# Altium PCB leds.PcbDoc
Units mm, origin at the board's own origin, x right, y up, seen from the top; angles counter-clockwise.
Board outline 80 x 58 mm, 2 copper layers (Top Layer, Bottom Layer), stack 1.579 mm thick; 53 components, 21 nets, 131 pads, 173 vias.
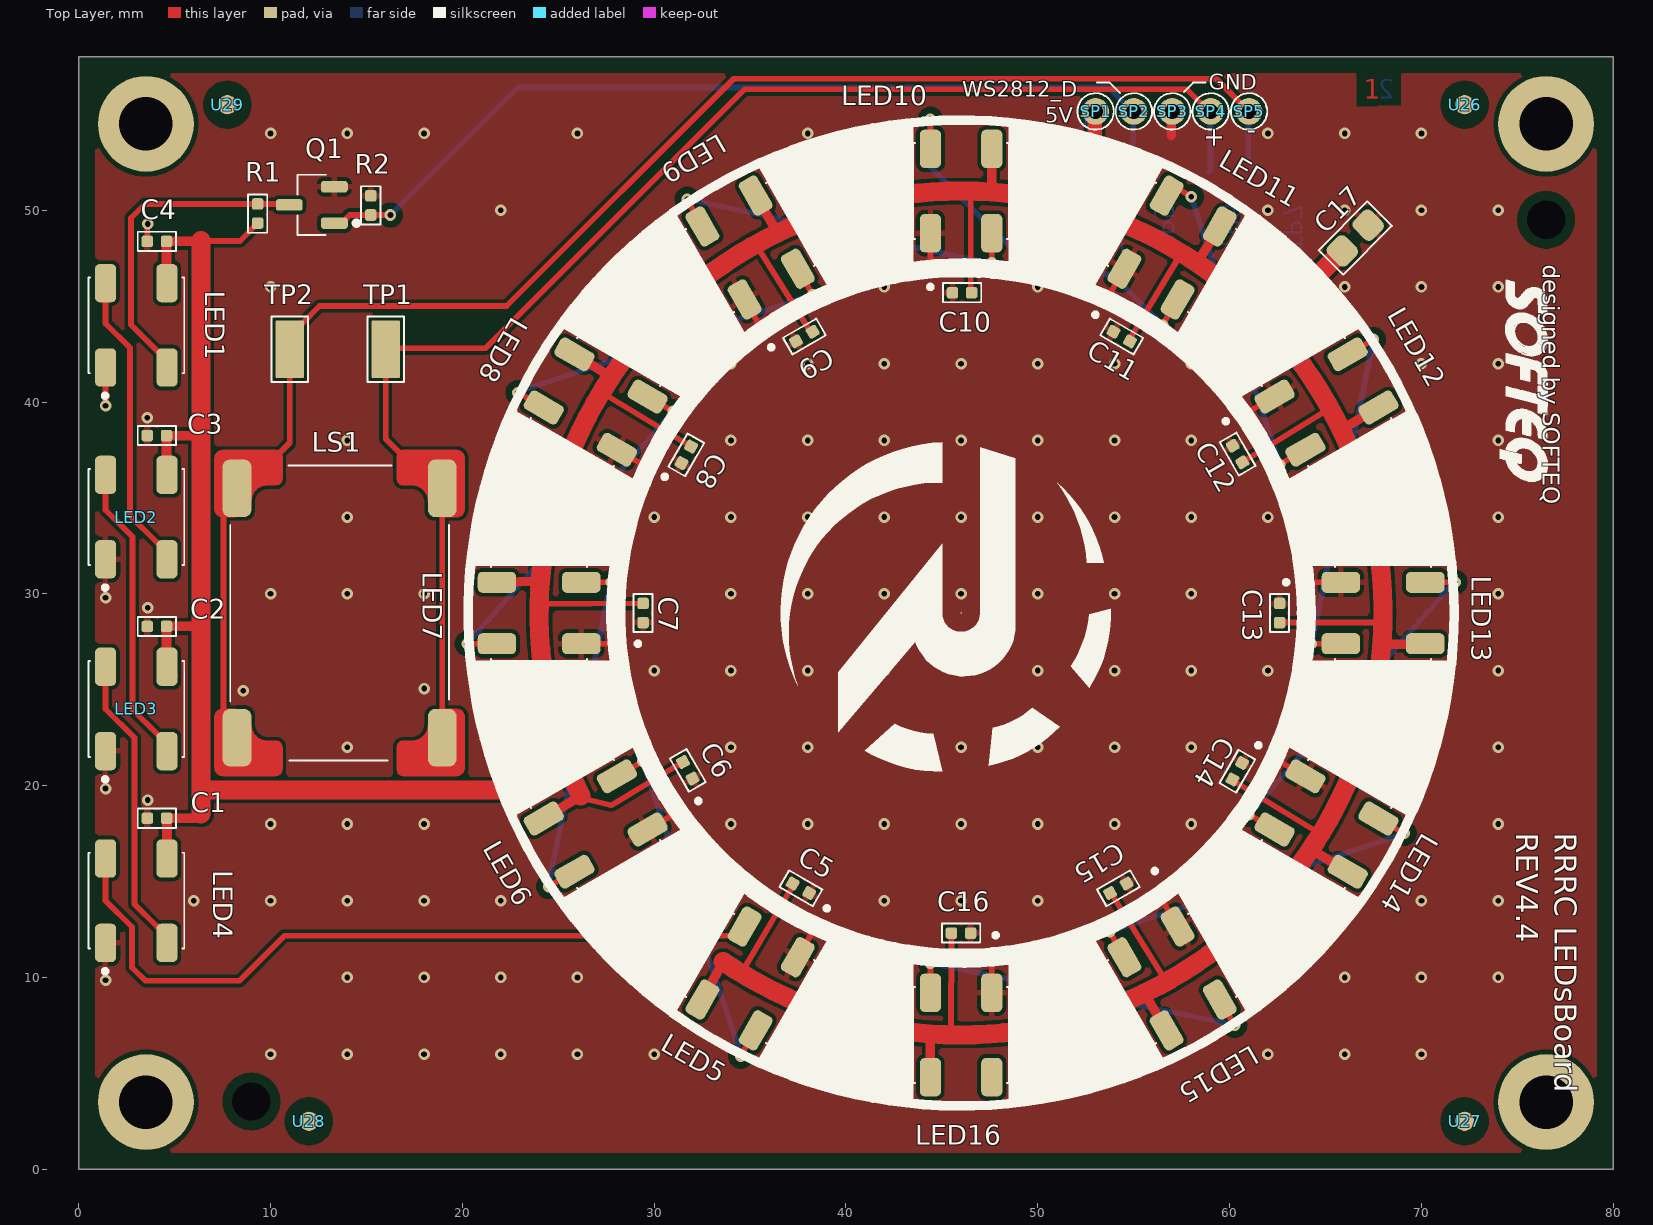
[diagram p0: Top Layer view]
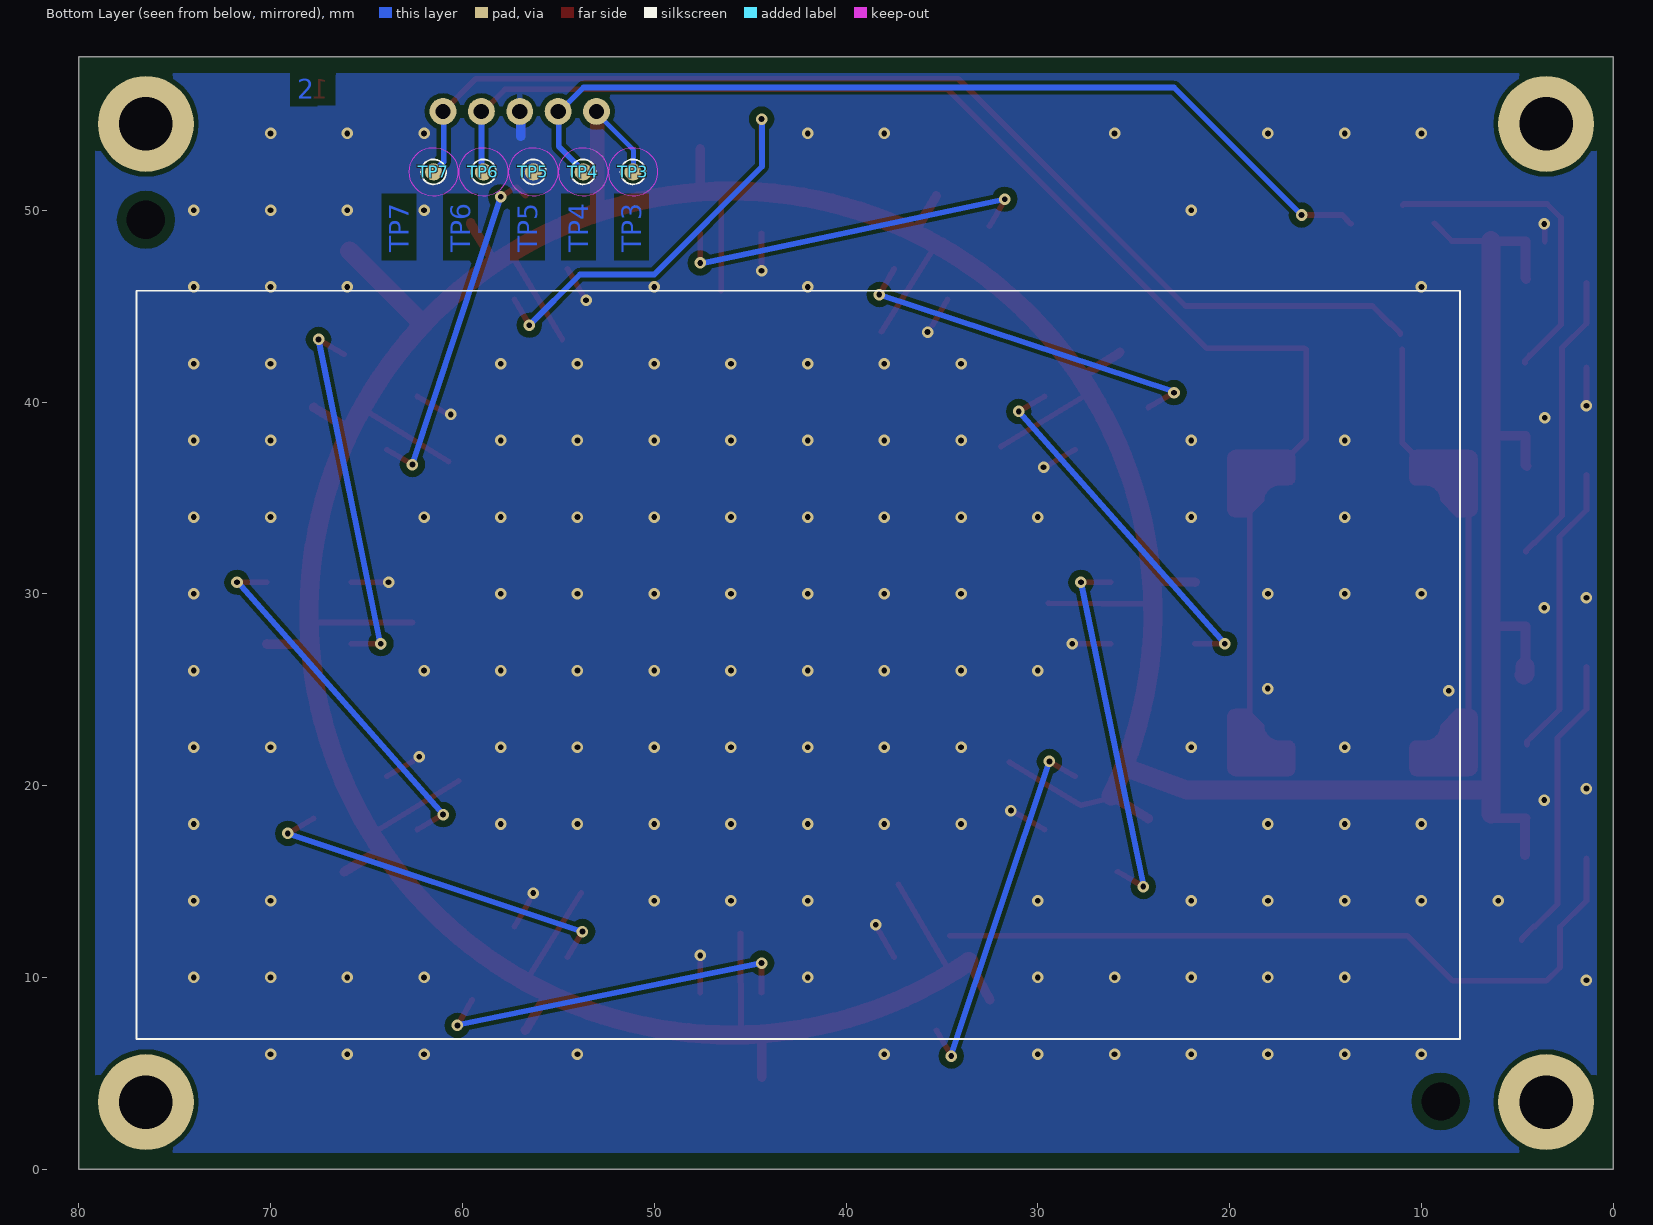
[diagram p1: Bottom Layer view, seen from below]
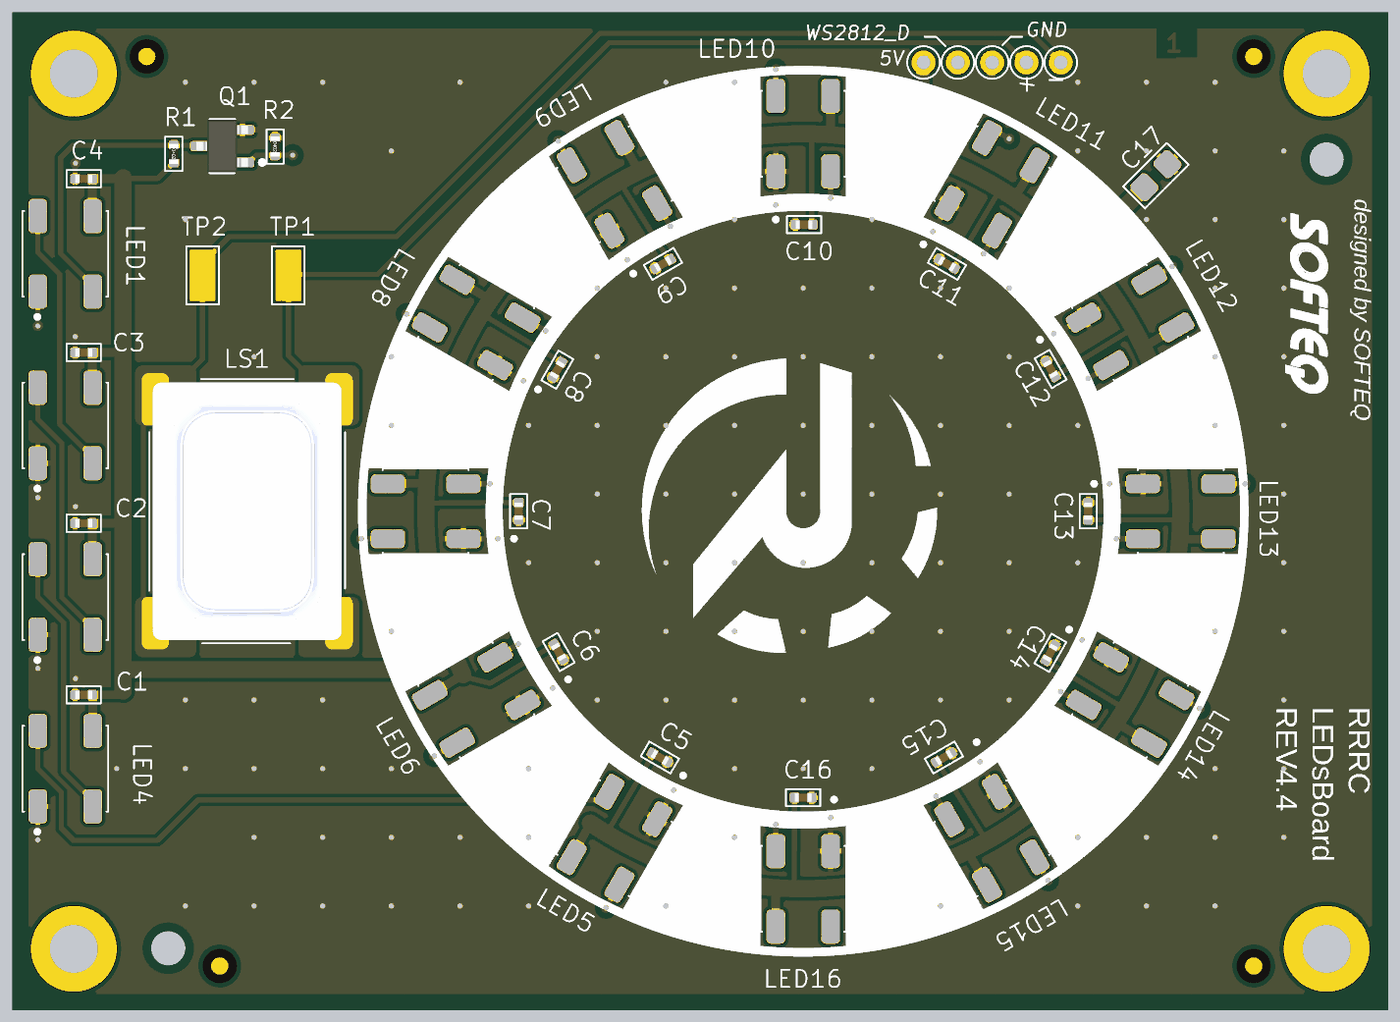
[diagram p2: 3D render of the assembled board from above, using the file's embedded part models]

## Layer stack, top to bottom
Top Solder: solder mask 0.02, Solder Resist, Dk 3.5
Top Layer: signal copper 0.04
Dielectric 1: core 1.4986, Core-043, Dk 4.3
Bottom Layer: signal copper 0.04
Bottom Solder: solder mask 0.02, Solder Resist, Dk 3.5

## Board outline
0,0 0,58 80,58 80,0

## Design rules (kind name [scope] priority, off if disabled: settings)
BoardOutlineClearance [OnSignal] p1: gap=0.85 ignorepadtopadclearanceinfootprint=FALSE
Clearance Clearance_samenet [IsPad vs IsVia] p1: gap=0.2 ignorepadtopadclearanceinfootprint=FALSE except(0.5: Fill-Fill Fill-Poly Fill-Region Poly-Poly Poly-Region Region-Region)
Clearance [All] p2: gap=0.2 ignorepadtopadclearanceinfootprint=FALSE except(0.25: THPad-Poly; 0.5: Poly-Hole)
ComponentClearance [All] p1 off: gap=0.254 collisioncheckmode=3 verticalgap=0.254 showdistances=FALSE
MinimumSolderMaskSliver [All] p1: minsoldermaskwidth=0.1
PasteMaskExpansion [All] p1: expansion=-0.025
PlaneConnect [All] p1: planeconnectstyle=Relief reliefexpansion=0.508 reliefentries=4 reliefconductorwidth=0.3 reliefairgap=0.2
PolygonConnect [All] p1: thpad.connectstyle=Relief thpad.reliefconductorwidth=0.3 thpad.reliefentries=4 thpad.polygonreliefangle="90 Angle" thpad.airgapwidth=0.2 smdpad.connectstyle=Relief smdpad.reliefconductorwidth=0.3 smdpad.reliefentries=4 smdpad.polygonreliefangle="90 Angle" smdpad.airgapwidth=0.2 via.connectstyle=Direct via.reliefconductorwidth=0.25 via.reliefentries=4 via.polygonreliefangle="90 Angle" via.airgapwidth=0.254
RoutingVias [All] p1: holewidth=0.3 width=0.6 viastyle="Through Hole" minholewidth=0.3 minwidth=0.6 maxholewidth=0.3 maxwidth=0.6
SilkToSilkClearance [All] p1: silktosilkclearance=0.1
SilkToSolderMaskClearance [IsPad] p1: minsilkscreentomaskgap=0.1 clearancetoexposedcopper=FALSE
SolderMaskExpansion [All] p1: expansion=0.05 istentingtop=FALSE
Width [All] p1: maxlimit=1 minlimit=0.2 preferedwidth=0.3
24 further rules are at their usual default settings.

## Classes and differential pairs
component class leds: C1 C2 C3 C4 C5 C6 C7 C8 C9 C10 C11 C12 C13 C14 C15 C16 C17 LED1 LED2 LED3 LED4 LED5 LED6 LED7 LED8 LED9 LED10 LED11 LED12 LED13 LED14 LED15 LED16 LS1 LS2 Q1 R1 R2 SP1 SP2 SP3 SP4 SP5 TP1 TP2 TP3 TP4 TP5 TP6 TP7

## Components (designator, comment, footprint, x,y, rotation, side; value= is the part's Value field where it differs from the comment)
C1 "CC0402KRX7R7BB104" C_0402 4.075,18.3 r0 top value=100n
C2 "CC0402KRX7R7BB104" C_0402 4.075,28.3 r0 top value=100n
C3 "CC0402KRX7R7BB104" C_0402 4.075,38.25 r0 top value=100n
C4 "CC0402KRX7R7BB104" C_0402 4.075,48.375 r0 top value=100n
C5 "CC0402KRX7R7BB104" C_0402 37.65,14.65 r150 top value=100n
C6 "CC0402KRX7R7BB104" C_0402 31.75,20.8 r120 top value=100n
C7 "CC0402KRX7R7BB104" C_0402 29.418,29 r90 top value=100n
C8 "CC0402KRX7R7BB104" C_0402 31.674,37.248 r60 top value=100n
C9 "CC0402KRX7R7BB104" C_0402 37.828,43.415 r30 top value=100n
C10 "CC0402KRX7R7BB104" C_0402 46.05,45.7 r0 top value=100n
C11 "CC0402KRX7R7BB104" C_0402 54.375,43.415 r330 top value=100n
C12 "CC0402KRX7R7BB104" C_0402 60.415,37.288 r300 top value=100n
C13 "CC0402KRX7R7BB104" C_0402 62.605,29 r270 top value=100n
C14 "CC0402KRX7R7BB104" C_0402 60.4,20.75 r240 top value=100n
C15 "CC0402KRX7R7BB104" C_0402 54.2,14.65 r210 top value=100n
C16 "CC0402KRX7R7BB104" C_0402 45.998,12.313 r180 top value=100n
C17 "CC0805KKX5R8BB106" C_0805 66.55,48.55 r225 top value=10u
LED1 "TJ-S5050RGBICSY62-A6" TONGJIA_TJ-S5050RGBICSY62-A6 3,44 r270 top locked
LED2 "TJ-S5050RGBICSY62-A6" TONGJIA_TJ-S5050RGBICSY62-A6 3,34 r270 top locked
LED3 "TJ-S5050RGBICSY62-A6" TONGJIA_TJ-S5050RGBICSY62-A6 3,24 r270 top locked
LED4 "TJ-S5050RGBICSY62-A6" TONGJIA_TJ-S5050RGBICSY62-A6 3,14 r270 top locked
LED5 "TJ-S5050RGBICSY62-A6" TONGJIA_TJ-S5050RGBICSY62-A6 35,9.95 r60 top locked
LED6 "TJ-S5050RGBICSY62-A6" TONGJIA_TJ-S5050RGBICSY62-A6 26.947,18 r30 top locked
LED7 "TJ-S5050RGBICSY62-A6" TONGJIA_TJ-S5050RGBICSY62-A6 24,29 r0 top locked
LED8 "TJ-S5050RGBICSY62-A6" TONGJIA_TJ-S5050RGBICSY62-A6 26.947,40 r330 top locked
LED9 "TJ-S5050RGBICSY62-A6" TONGJIA_TJ-S5050RGBICSY62-A6 35,48.053 r300 top locked
LED10 "TJ-S5050RGBICSY62-A6" TONGJIA_TJ-S5050RGBICSY62-A6 46,51 r270 top locked
LED11 "TJ-S5050RGBICSY62-A6" TONGJIA_TJ-S5050RGBICSY62-A6 57,48.053 r240 top locked
LED12 "TJ-S5050RGBICSY62-A6" TONGJIA_TJ-S5050RGBICSY62-A6 65.053,40 r210 top locked
LED13 "TJ-S5050RGBICSY62-A6" TONGJIA_TJ-S5050RGBICSY62-A6 68,29 r180 top locked
LED14 "TJ-S5050RGBICSY62-A6" TONGJIA_TJ-S5050RGBICSY62-A6 65.053,18 r150 top locked
LED15 "TJ-S5050RGBICSY62-A6" TONGJIA_TJ-S5050RGBICSY62-A6 57,9.947 r120 top locked
LED16 "TJ-S5050RGBICSY62-A6" TONGJIA_TJ-S5050RGBICSY62-A6 46,7 r90 top locked
LS1 "HTD-S1511-30LH-003" SHENZHENTONGHUIDA_TECH_HTD-S1511-30LH-003 13.6,29 r180 top locked
Q1 "NX7002AK,215" SOT-23-3 12.15,50.275 r180 top
R1 "RC0402FR-074K7L" R_0402 9.325,49.825 r270 top value=4.7K
R2 "RC0402FR-0747KL" R_0402 15.225,50.25 r270 top value=47K
SP1 "\"5V\"" THSP_0.8_1.4 53.01,55.15 r0 top
SP2 "\"WS2812_D\"" THSP_0.8_1.4 55.01,55.15 r0 top
SP3 "\"GND\"" THSP_0.8_1.4 57.01,55.15 r0 top
SP4 "\"SPK+\"" THSP_0.8_1.4 59.01,55.15 r0 top
SP5 "\"SPK-\"" THSP_0.8_1.4 61.01,55.15 r0 top
TP1 "" SSP_1.5x3.0 16,42.75 r270 top
TP2 "" SSP_1.5x3.0 11,42.75 r270 top
TP3 "" STP_0.9 51.1,52 r180 bottom
TP4 "" STP_0.9 53.7,52 r180 bottom
TP5 "" STP_0.9 56.3,52 r180 bottom
TP6 "" STP_0.9 58.9,52 r180 bottom
TP7 "" STP_0.9 61.5,52 r180 bottom
U26 "Comment" FEDUCIAL 72.25,55.5 r270 top
U27 "Comment" FEDUCIAL 72.25,2.5 r270 top
U28 "Comment" FEDUCIAL 12,2.5 r270 top
U29 "Comment" FEDUCIAL 7.75,55.5 r270 top

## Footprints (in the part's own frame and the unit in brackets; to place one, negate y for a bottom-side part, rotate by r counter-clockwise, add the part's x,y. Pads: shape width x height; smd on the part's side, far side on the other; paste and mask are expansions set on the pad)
C_0402 [mm]
  rrect40% 0.6x0.6 smd paste-0.025 mask+0.05: 1(-0.5,0) 2(0.5,0)
  silkscreen extent -1,-0.5 1,0.5, body extent -0.5,-0.25 0.5,0.25, height 0.5
C_0805 [mm]
  rrect50% 1.3x1.4 smd paste-0.025 mask+0.05: 1(-0.95,0) 2(0.95,0)
  silkscreen extent -1.8,-0.9 1.8,0.9, body extent -1,-0.6 1,0.6, height 1.45
FEDUCIAL [mm]
  round 1 smd paste-1 mask+0.5: FED(0,0)
  Top Layer pour cut-out: 0,1.25 0.478,1.155 0.884,0.884 1.155,0.478 1.25,0 1.25,0 1.155,-0.478 0.884,-0.884 0.478,-1.155 0,-1.25 0,-1.25 -0.478,-1.155 -0.884,-0.884 -1.155,-0.478 -1.25,0 -1.25,0 -1.155,0.478 -0.884,0.884 -0.478,1.155 0,1.25
R_0402 [mm]
  rrect40% 0.6x0.6 smd paste-0.025 mask+0.05: 1(-0.5,0) 2(0.5,0)
  silkscreen extent -1,-0.5 1,0.5, body extent -0.57,-0.27 0.58,0.28, height 0.41
SHENZHENTONGHUIDA_TECH_HTD-S1511-30LH-003 [mm]
  rrect50% 1.5x3 smd paste-1 mask+0.05: 1(-5.35,-6.5) 2(5.35,-6.5)
  silkscreen extent -5.7,-7.7 5.7,7.7, body extent -5.5,-7.5 5.5,7.5, height 3.51
SOT-23-3 [mm] "Small Outline Transistor (SOT23), 0.95 mm pitch; 3 pin, 2.90 mm L X 1.475 mm W X 1.40 mm H body"
  rrect50% 1.4x0.6 smd paste-0.025 mask+0.05: 1(-1.175,0.95) 2(-1.175,-0.95) 3(1.175,0)
  silkscreen extent -2.45,-1.58 0.74,1.58, body extent -1.5,-1.52 1.5,1.52, height 1.4
SSP_1.5x3.0 [mm]
  rrect10% 3x1.5 smd paste-1.6 mask+0.05: 1(0,0)
  silkscreen extent -1.7,-0.95 1.7,0.95
STP_0.9 [mm]
  round 0.9 smd paste-1 mask+0.05: 1(0,0)
  Top Layer keep-out circle w0.025: c0,0 r1.27
  silkscreen extent -0.65,-0.65 0.65,0.65
THSP_0.8_1.4 [mm]
  round 1.4 hole 0.8 paste-2539.97 mask+0.05: 1(0,0)
  silkscreen extent -0.95,-0.95 0.95,0.95
TONGJIA_TJ-S5050RGBICSY62-A6 [mm]
  rrect45% 2x1.1 smd paste-0.025 mask+0.05: 1(-2.2,1.6) 2(-2.2,-1.6) 3(2.2,-1.6) 4(2.2,1.6)
  silkscreen extent -2.5,-2.5 3.77,2.5, body extent -2.5,-2.5 2.5,2.5, height 1.6

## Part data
C1 C2 C3 C4 C5 C6 C7 C8 C9 C10 C11 C12 C13 C14 C15 C16: "Capacitor, 100nF, 10%, 16V, X7R, -55/+125,0402", Manufacturer=Yageo
C17: "Capacitor, 10uF, 10%, 25V, X5R, -55/+85, 0805", Manufacturer=Yageo
LED1 LED2 LED3 LED4 LED5 LED6 LED7 LED8 LED9 LED10 LED11 LED12 LED13 LED14 LED15 LED16: "LED, RGB, 3.5-5.5V, SK6812 Serial Interface, 5050, -40/+85, SMD", Manufacturer="TAIWAN TONGJIA OPTOELECTRONICS TECHNOLOGY"
LS1: "Speaker, magnetic, spring, 8 Ohm, 0.7W, 300Hz-20kHz, Top Rectangular, 85dB", Manufacturer="SHENZHENTONGHUIDA TECHNOLOGY"
Q1: "MOSFET, N-CH, 60V, 190mA, -55/+150, TO-236AB", Manufacturer=Nexperia
R1: "Resistor, 4.7K, 1%, 0.063W, -55/+155, 0402", Manufacturer=Yageo
R2: "Resistor, 47K, 1%, 0.063W, -55/+155, 0402", Manufacturer=Yageo
SP1 SP2 SP3 SP4 SP5: library part SolderPoint_TH_0.8x1.4, "Solder Point, 0.8mm hole, 1.4mm pad, TH"
TP1 TP2: library part SolderPoint_1.5x3.0
TP3 TP4 TP5 TP6 TP7: library part TestPoint_SMD_0.9

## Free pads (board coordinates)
  rrect50% 1.5x3 smd paste-1 mask+0.05: 1(18.95,22.5) 2(8.25,22.5)
  round 5 hole 2.8 mask+0.05: MH(3.5,3.5) MH(3.5,54.5) MH(76.5,3.5) MH(76.5,54.5)
  round 0 hole 2 unplated mask+0.25: TH(9,3.533) TH(76.5,49.5)

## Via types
v1: diameter 0.6, hole 0.3, Top Layer to Bottom Layer, tented both sides, 173 vias

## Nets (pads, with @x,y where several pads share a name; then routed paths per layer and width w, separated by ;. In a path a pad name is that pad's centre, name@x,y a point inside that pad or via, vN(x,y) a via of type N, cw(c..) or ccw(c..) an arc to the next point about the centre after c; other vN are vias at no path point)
5V: C1.2 C2.2 C3.2 C4.2 C5.2 C6.2 C7.2 C8.2 C9.2 C10.2 C11.2 C12.2 C13.2 C14.2 C15.2 C16.2 C17.2 LED1.1 LED2.1 LED3.1 LED4.1 LED5.1 LED6.1 LED7.1 LED8.1 LED9.1 LED10.1 LED11.1 LED12.1 LED13.1 LED14.1 LED15.1 LED16.1 R1.2 SP1.1 TP3.1 | length 301.6
  Top Layer w0.3: 6.6,48.4 8.4,48.4 R1.2 ; 24,29.475 24.005,29.475 29.418,29.506 C7.2@29.45,29.506 ; 26.15,19.375 27.75,18.975 28.1,19.175 31.451,21.205 C6.2@31.485,21.225 ; 27.3,40.475 31.923,37.679 C8.2@31.927,37.677 ; 34.675,10.45 C5.2@37.259,14.845 ; 35.35,48.125 C9.2@38.151,43.669 ; 45.475,7.125 C16.2@45.5,12.3 ; C10.2@46.5,45.8 46.5,50.8 ; C15.2@53.808,14.405 56.675,9.8 ; C11.2@54.793,43.254 57.4,47.625 ; C14.2@60.2,20.251 64.742,17.48 64.75,17.475 ; C12.2@60.722,36.895 65.225,39.65 ; C13.2@62.6,28.5 C13.2 67.975,28.5 67.994,28.5 68.2,28.5
  Top Layer w0.5: LED2.1@4.5,36.65 4.575,36.725 C3.2 6.375,38.25 6.6,38.25 ; LED1.1@4.525,46.4 4.575,46.45 C4.2 6.375,48.375 6.5,48.375 ; LED4.1@4.6,16.375 4.6,18.275 C1.2 6.325,18.3 ; LED3.1@4.675,26.5 4.575,26.6 C2.2 6.375,28.3 6.55,28.3 ; LED7.1 24.062,30.645 ; LED6.1 26.17,19.472 ; LED8.1@25.727,42.601 LED8.1 27.764,41.307 ; LED5.1@32.514,8.842 LED5.1 33.601,10.827 ; LED9.1 36.443,48.816 ; 44.395,7.059 LED16.1 ; 47.594,50.942 47.6,50.948 LED10.1 ; 55.551,9.182 LED15.1 ; 58.298,47.242 LED11.1 ccw(c59.304,49.34) LED11.1@59.561,49.34 ; 64.232,16.687 LED14.1 ; 65.82,38.548 LED12.1 ; 67.975,27.375 70.2,27.375 LED13.1
  Top Layer w0.75: SP1.1@52.96,55.125 52.96,49.94 53,49.9
  Top Layer w1: LED3.1 4.6,25.825 LED3.1@4.65,25.775 ; 6.375,18.525 6.375,28.3 6.375,38.25 6.375,48.375 6.375,48.425 ; 6.375,19.775 22.253,19.775 25.513,20.981 ; 26.17,19.472 cw(c46,29) 25.513,20.981 ; 33.601,10.827 ccw(c46,29) 44.395,7.059 ccw(c46,29) 55.551,9.182 ccw(c46,29) 64.232,16.687 ccw(c46,29) 64.742,17.48 ccw(c46,29) 67.975,27.951 ; 62.075,44.125 62.125,44.125 C17.2 ; 67.975,27.375 67.975,27.951 ; 67.975,28.5 67.975,27.951 ; 25.513,20.981 cw(c46,29) 24.005,29.475 cw(c46,29) 24.062,30.645 cw(c46,29) 27.764,41.307 cw(c46,29) 36.443,48.816 cw(c46,29) 46,51 cw(c46,29) 47.594,50.942 cw(c46,29) 58.298,47.242 cw(c46,29) 65.82,38.548 cw(c46,29) 67.994,28.5 cw(c46,29) 67.975,27.951
  Bottom Layer w0.25: TP3.1@51.075,52.025 51.075,53.125 52.9,54.95 SP1.1@52.96,54.95
DOUT_LED4: LED4.2 LED5.4 | length 39.3
  Top Layer w0.3: LED4.2 1.4,14 2.775,12.625 2.775,10.525 3.475,9.825 8.375,9.825 10.725,12.175 LED5.4@34.575,12.175
DOUT_LED8: LED8.2 LED9.4 | length 19.2
  Top Layer w0.3: v1(22.9,40.489) LED8.2 ; LED9.4 v1(38.261,45.605)
  Bottom Layer w0.3: v1@22.95,40.55 v1(38.261,45.605)
DOUT_LED12: LED12.2 LED13.4 | length 19.5
  Top Layer w0.3: v1(64.25,27.4) LED13.4 ; LED12.2 v1(67.5,43.261)
  Bottom Layer w0.3: v1@64.25,27.225 64.284,27.393 v1(67.5,43.261)
GND: C1.1 C2.1 C3.1 C4.1 C5.1 C6.1 C7.1 C8.1 C9.1 C10.1 C11.1 C12.1 C13.1 C14.1 C15.1 C16.1 C17.1 LED1.3 LED2.3 LED3.3 LED4.3 LED5.3 LED6.3 LED7.3 LED8.3 LED9.3 LED10.3 LED11.3 LED12.3 LED13.3 LED14.3 LED15.3 LED16.3 Q1.2 R2.1 SP3.1 TP5.1 | length 25.5
  Top Layer w0.3: v1(1.4,39.8) LED1.3 ; C4.1 3.575,49.264 v1(3.595,49.284) ; LED7.3 v1@28.075,27.4 ; LED8.3 29.395,36.739 ; LED6.3 v1@31.226,18.623 ; LED9.3 35.489,44.005 ; LED5.3@37.486,11.053 37.487,11.055 v1@38.426,12.681 ; 44.4,47.25 LED10.3 ; LED16.3 47.6,10.75 ; 53.739,45.605 LED11.3 ; 56.511,13.995 LED15.3 ; v1@60.875,39.425 LED12.3 ; 62.605,21.261 LED14.3 ; v1(63.85,30.6) 64.2,30.6 64.225,30.575 64.25,30.6 LED13.3
  Top Layer w0.5: 56.95,53.9 56.96,53.91 SP3.1@56.96,55.125
  Bottom Layer w0.5: 56.95,53.85 56.96,53.86 SP3.1@56.96,55.125
  other v1: 10,6 14,6 18,6 22,6 26,6 30,6 38,6 54,6 62,6 66,6 70,6 1.4,9.85 14,10 18,10 22,10 26,10 30,10 42,10 62,10 66,10 70,10 74,10 47.6,11.15 38.45,12.75 6,14 10,14 14,14 18,14 22,14 30,14 42,14 46,14 50,14 70,14 74,14 56.3,14.4 10,18 14,18 18,18 34,18 38,18 42,18 46,18 50,18 54,18 58,18 74,18 31.4,18.7 3.595,19.25 1.4,19.85 62.25,21.5 14,22 22,22 34,22 38,22 42,22 46,22 50,22 54,22 58,22 70,22 74,22 8.577,24.945 18.014,25.059 30,26 34,26 38,26 42,26 46,26 50,26 54,26 58,26 62,26 74,26 28.2,27.4 3.595,29.27 1.4,29.8 10,30 14,30 18,30 34,30 38,30 42,30 46,30 50,30 54,30 58,30 74,30 14,34 22,34 30,34 34,34 38,34 42,34 46,34 50,34 54,34 58,34 62,34 70,34 74,34 29.7,36.6 14,38 22,38 34,38 38,38 42,38 46,38 50,38 54,38 58,38 70,38 74,38 3.575,39.175 60.6,39.35 34,42 38,42 42,42 46,42 50,42 54,42 58,42 70,42 74,42 35.75,43.65 53.55,45.3 10,46 42,46 50,46 66,46 70,46 74,46 44.4,46.85 22,50 62,50 66,50 70,50 74,50 10,54 14,54 18,54 26,54 38,54 42,54 62,54 66,54 70,54
NetLED1_2: LED1.2 LED2.4 | length 15.3
  Top Layer w0.3: LED1.2 1.4,44.1 2.675,42.825 2.675,34.075 4.1,32.65 4.147,32.65 4.55,32.247 LED2.4@4.55,32.2
NetLED1_4: LED1.4 Q1.3 R1.1 | length 16.9
  Top Layer w0.3: LED1.4@4.375,42.422 LED1.4@4.375,42.375 ; LED1.4@4.6,42.05 4.6,42.15 LED1.4@4.375,42.375 ; Q1.3 10.925,50.325 3.45,50.325 2.725,49.6 2.725,44.025 LED1.4@4.375,42.375
NetLED2_2: LED2.2 LED3.4 | length 15.3
  Top Layer w0.3: LED2.2 1.4,34.375 2.8,32.975 2.8,23.975 4.125,22.65 4.147,22.65 4.5,22.297 LED3.4@4.5,22.15
NetLED3_2: LED3.2 LED4.4 | length 15.7
  Top Layer w0.3: LED3.2 1.4,24 2.907,22.493 2.907,13.818 4.075,12.65 4.147,12.65 4.775,12.022 LED4.4@4.775,11.95
NetLED5_2: LED5.2 LED6.4 | length 19.3
  Top Layer w0.3: LED6.4 v1(29.395,21.261) ; v1(34.511,5.9) LED5.2@35.286,7.242
  Bottom Layer w0.3: v1(29.395,21.261) 34.539,5.909 v1@34.55,5.875
NetLED6_2: LED6.2 LED7.4 | length 19.3
  Top Layer w0.3: v1(24.5,14.739) LED6.2 ; LED7.4 v1(27.75,30.6)
  Bottom Layer w0.3: v1@24.475,14.75 v1(27.75,30.6)
NetLED7_2: LED7.2 LED8.4 | length 19.3
  Top Layer w0.3: v1(20.25,27.4) LED7.2 ; LED8.4 v1(30.995,39.511)
  Bottom Layer w0.3: v1@20.225,27.375 20.248,27.401 v1(30.995,39.511)
NetLED9_2: LED9.2 LED10.4 | length 19.3
  Top Layer w0.3: v1@31.739,50.5 LED9.2 ; v1(47.6,47.25) LED10.4
  Bottom Layer w0.3: v1(31.725,50.575) v1@47.55,47.225
NetLED10_2: LED10.2 LED11.4 | length 21.2
  Top Layer w0.3: LED10.2 v1(44.4,54.75) ; v1(56.511,44.005) LED11.4
  Bottom Layer w0.3: v1@44.375,54.825 44.375,52.275 50,46.65 53.866,46.65 v1(56.511,44.005)
NetLED11_2: LED11.2 LED12.4 | length 17.9
  Top Layer w0.3: LED11.2 57.157,51.2 57.2,51.2 v1(58,50.7) ; v1(62.605,36.739) LED12.4
  Bottom Layer w0.3: v1(58,50.7) v1(62.605,36.739)
NetLED13_2: LED13.2 LED14.4 | length 19.3
  Top Layer w0.3: v1(61.005,18.489) LED14.4 ; LED13.2 v1(71.75,30.6)
  Bottom Layer w0.3: v1(61.005,18.489) v1@71.7,30.625
NetLED14_2: LED14.2 LED15.4 | length 19.3
  Top Layer w0.3: v1(53.739,12.395) LED15.4 ; LED14.2 v1(69.1,17.511)
  Bottom Layer w0.3: v1(53.739,12.395) v1@69.075,17.5
NetLED15_2: LED15.2 LED16.4 | length 19.3
  Top Layer w0.3: LED16.4 v1(44.4,10.75) ; LED15.2 v1(60.261,7.5)
  Bottom Layer w0.3: v1(44.4,10.75) v1@60.225,7.525
NetLS1_1: LS1.1 pad.1 SP4.1 TP1.1 TP6.1 | length 73.6
  Top Layer w0.3: TP1.1 16,38.075 17.926,36.149 18.367,36.149 18.7,35.816 LS1.1@18.7,35.5 ; TP1.1@16.1,42.8 21.2,42.8 34.7,56.3 57.775,56.3 SP4.1@58.9,55.175 ; pad.1 LS1.1
  Bottom Layer w0.3: TP6.1 59,52.1 SP4.1@59,55.075
NetLS1_2: LS1.2 pad.2 SP5.1 TP2.1 TP7.1 | length 81.8
  Top Layer w0.3: pad.2 8.25,22.967 7.667,23.55 7.55,23.55 7.55,34.45 7.667,34.45 8.25,35.033 LS1.2 8.833,36.149 9.274,36.149 11,37.875 TP2.1 ; TP2.1@11.1,43.55 11.1,43.6 11.6,44.1 11.65,44.1 12.55,45 22.3,45 34.15,56.85 59.3,56.85 SP5.1@60.95,55.2
  Bottom Layer w0.3: SP5.1@60.975,55.15 60.975,52.525 TP7.1
WS2812_D: Q1.1 R2.2 SP2.1 TP4.1 | length 48.3
  Top Layer w0.3: Q1.1@13.675,49.3 13.7,49.3 13.875,49.475 13.875,49.5 14.125,49.75 R2.2 v1@16.15,49.75
  Bottom Layer w0.3: v1(16.25,49.75) 22.9,56.4 53.685,56.4 SP2.1@54.96,55.125 ; TP4.1@53.675,52.025 54.975,53.325 SP2.1@54.975,55.15
pads on no net: LED16.2 U26.FED U27.FED U28.FED U29.FED

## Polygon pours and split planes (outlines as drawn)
GND on Bottom Layer "GND_L02_P000" (solid, remove dead copper, pour order 0): 0,0 0,58 80,58 80,0
no net on Bottom Solder "NONET_L-01_P-001" (solid): 77,19.05 77,6.8 62.25,6.8 62.25,8.301 75.5,8.303 75.5,19.05
no net on Bottom Solder "NONET_L-01_P-001" (solid): 30.65,45.8 8,45.8 8,35.6 9.502,35.6 9.503,44.3 30.65,44.3
no net on Bottom Solder "NONET_L-01_P-001" (solid): 77,33.55 77,45.8 62.25,45.8 62.25,44.299 75.5,44.297 75.5,33.55
no net on Bottom Solder "NONET_L-01_P-001" (solid): 8,19.05 8,6.8 30.75,6.8 30.75,8.3 9.5,8.303 9.5,19.05
GND on Top Layer "GND_L01_P005" (solid, remove dead copper, pour order 5): 0,0 0,58 80,58 80,0

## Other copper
Top Layer:
  region net NetLS1_1: 16.575,22 cw(c16.925,22) 16.925,22.35 17.375,22.35 ccw(c17.375,23.175) 18.2,23.175 19.025,24 19.725,24 cw(c19.725,23.6) 20.125,23.6 20.125,20.925 cw(c19.7,20.925) 19.7,20.5 16.925,20.5 cw(c16.925,20.85) 16.575,20.85
  region net NetLS1_2: 10.625,22 ccw(c10.275,22) 10.275,22.35 9.825,22.35 cw(c9.825,23.175) 9,23.175 8.175,24 7.475,24 ccw(c7.475,23.6) 7.075,23.6 7.075,20.925 ccw(c7.5,20.925) 7.5,20.5 10.275,20.5 ccw(c10.275,20.85) 10.625,20.85
  region net NetLS1_2: 10.625,36 cw(c10.275,36) 10.275,35.65 9.825,35.65 ccw(c9.825,34.825) 9,34.825 8.175,34 7.475,34 cw(c7.475,34.4) 7.075,34.4 7.075,37.075 cw(c7.5,37.075) 7.5,37.5 10.275,37.5 cw(c10.275,37.15) 10.625,37.15
  region net NetLS1_1: 16.575,36 ccw(c16.925,36) 16.925,35.65 17.375,35.65 cw(c17.375,34.825) 18.2,34.825 19.025,34 19.725,34 ccw(c19.725,34.4) 20.125,34.4 20.125,37.075 ccw(c19.7,37.075) 19.7,37.5 16.925,37.5 ccw(c16.925,37.15) 16.575,37.15
  text "1" at 67,55.8 h1
Bottom Layer:
  text "2" at 68.6,55.8 h1
Multi-Layer:
  pour cut-out: 66.6,56.95 68.95,56.95 68.95,55.45 66.6,55.45

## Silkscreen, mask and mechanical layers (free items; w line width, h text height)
Top Overlay:
  drawing of 542 lines, arcs and shapes, not listed
  text "GND" at 58.925,56.275 h0.8
  text "WS2812_D" at 46.05,55.925 h0.8
  text "5V" at 50.375,54.55 h0.8
  text "-" at 61.4,54.45 h1 r180
  text "+" at 59.625,53.2 h1 r90
  text "designed by SOFTEQ" at 76.05,47.15 h1.5 r270
  text "RRRC LEDsBoard / REV4.4" at 74.55,17.55 h2 r270
Bottom Overlay:
  lines w0.1: 8,6.8 8,45.8 77,45.8 77,6.8 8,6.8
Bottom Solder:
  text "BATTERY GLUE AREA" at 62.8,23.95 h2.5
Top Assembly:
  text "ASSEMBLY DRAWING TOP" at 11.27,-6.725 h2.5
  text "Unplaced (DNP) components are crossed" at 2.37,-10 h2
Mechanical 2:
  drawing of 486 lines, arcs and shapes, not listed
BoardOutline:
  the board outline again, w0.15
Top Courtyard:
  drawing of 137 lines, arcs and shapes, not listed
PCB_INFO:
  drawing of 191 lines, arcs and shapes, not listed
  text "Layer" at 85.339,78.2 h1
  text "Name" at 92.038,78.2 h1
  text "Material" at 107.4,78.2 h1
  text "Thickness" at 121.596,78.2 h1
  text "Constant" at 132.293,78.2 h1
  text "Board Layer Stack" at 141.658,78.2 h1
  text "Top Overlay" at 92.038,76.2 h1
  text "Top Solder" at 92.038,74.2 h1
  text "Solder Resist" at 107.4,74.2 h1
  text "0.020mm" at 121.596,74.2 h1
  text "3.5" at 132.293,74.2 h1
  text "1" at 85.339,72.2 h1
  text "Top Layer" at 92.038,72.2 h1
  text "0.040mm" at 121.596,72.2 h1
  text "Dielectric 1" at 92.038,70.2 h1
  text "Core-043" at 107.4,70.2 h1
  text "1.499mm" at 121.596,70.2 h1
  text "4.3" at 132.293,70.2 h1
  text "2" at 85.339,68.2 h1
  text "Bottom Layer" at 92.038,68.2 h1
  text "0.040mm" at 121.596,68.2 h1
  text "Bottom Solder" at 92.038,66.2 h1
  text "Solder Resist" at 107.4,66.2 h1
  text "0.020mm" at 121.596,66.2 h1
  text "3.5" at 132.293,66.2 h1
  text "Bottom Overlay" at 92.038,64.2 h1
  text "PCB NOTES" at 84.325,57.806 h1.5
  text "1. Number of layers - 2" at 84.175,53.656 h1.5
  text "2. Board size - 80mm x 58mm. Tolerance - +/- 0.1mm" at 84.175,50.656 h1.5
  text "3. Board thickness - 1.6mm +/-10%" at 84.175,47.656 h1.5
  text "4. Material - FR-4 High Tg, cooper thickness is 35um (1oz)" at 84.175,44.656 h1.5
  text "5. Solder Mask - Two sides, Green, Liquid. Solder mask mis-registration +/-0.025mm. /    No overlap permitted on SMD lands. Solder Mask is in accordance  /    with IPC-SM-840 D, Class H" at 84.175,35.656 h1.5
  text "6. Silkscreen - TOP side only" at 84.175,32.656 h1.5
  text "7. Type of coating - ENIG" at 84.175,29.656 h1.5
  text "8. Electrical Test on both sides" at 84.175,26.406 h1.5
  text "9. Min dia of plated hole - 0.3mm" at 84.175,23.406 h1.5
  text "10. Min annular ring  - 0.15mm" at 84.175,19.906 h1.5
  text "11. Min trace width -  0.2mm" at 84.175,16.906 h1.5
  text "12. Min clearance -  0.2mm" at 84.425,13.406 h1.5
  text "13. Impedance control - No" at 84.45,10.45 h1.5
Drill Drawing:
  lines w0.15: -7.125,69.775 88.249,69.775 ; -7.125,84.775 88.249,84.775 ; 6.327,66.025 6.327,88.525 ; 23.452,66.025 23.452,88.525 ; 56.772,66.025 56.772,88.525 ; 69.099,66.025 69.099,88.525 ; -7.125,66.025 88.249,66.025 88.249,88.525 -7.125,88.525 -7.125,66.025 ; -5.661,70.9 -4.828,71.317 -3.995,70.9 -4.411,71.733 -3.995,72.567 -4.828,72.15 -5.661,72.567 -5.245,71.733 -5.661,70.9 ; -5.661,75.067 -5.245,75.067 -4.828,74.65 -4.411,75.067 -3.995,75.067 -4.411,75.483 -3.995,75.9 -4.411,75.9 -4.828,76.317 -5.245,75.9 -5.661,75.9 -5.245,75.483 -5.661,75.067 ; -5.661,78.4 -3.995,78.4 -3.995,80.067 -5.661,80.067 -5.661,78.4 ; -5.661,83.817 -3.995,83.817 -4.828,82.15 -5.661,83.817
  text "Symbol" at -4.875,85.9 h1.8
  text "Hit Count" at 7.452,85.9 h1.8
  text "Finished Hole Size" at 24.577,85.9 h1.8
  text "Plated" at 57.897,85.9 h1.8
  text "Hole Type" at 70.224,85.9 h1.8
  text "173" at 7.452,82.15 h1.5
  text "0.300mm" at 24.577,82.15 h1.5
  text "PTH" at 57.897,82.15 h1.5
  text "Round" at 70.224,82.15 h1.5
  text "5" at 7.452,78.4 h1.5
  text "0.800mm" at 24.577,78.4 h1.5
  text "PTH" at 57.897,78.4 h1.5
  text "Round" at 70.224,78.4 h1.5
  text "2" at 7.452,74.65 h1.5
  text "2.000mm" at 24.577,74.65 h1.5
  text "NPTH" at 57.897,74.65 h1.5
  text "Round" at 70.224,74.65 h1.5
  text "4" at 7.452,70.9 h1.5
  text "2.800mm" at 24.577,70.9 h1.5
  text "PTH" at 57.897,70.9 h1.5
  text "Round" at 70.224,70.9 h1.5
  text "184 Total" at 7.452,67.15 h1.5

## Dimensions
0,58 to 0,0 on PCB_INFO
0,58 to 80,58 on PCB_INFO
